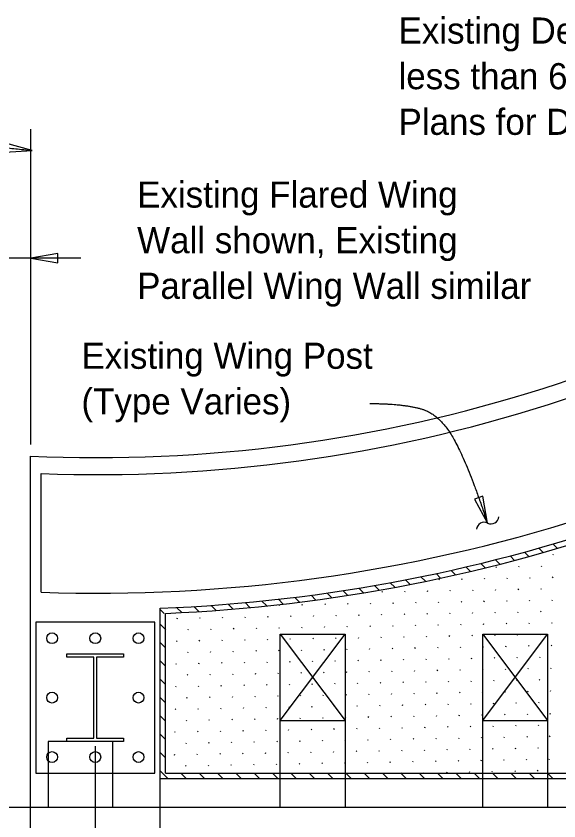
# Model space of a CAD drawing. Extents: x 21526.6 to 21595.9, y 56117 to 56157.3.
# Drawn here: x 21554.19 to 21558.38, y 56146.9 to 56153.11 of the extents above; entities that cross this region are included whole.
import ezdxf

# ---------------------------------------------------------------- set-up
doc = ezdxf.new("R2010")
doc.units = 0
for name, color, linetype in [('AdhocPoint_dp', 7, 'Continuous'), ('Patterning', 7, 'Continuous'), ('PlotBorder_dp', 7, 'Continuous'), ('SheetBorder_dp', 7, 'Continuous')]:
    doc.layers.add(name, color=color, linetype=linetype)

msp = doc.modelspace()

# ---------------------------------------------------------------- linework, layer by layer
at = {"layer": 'AdhocPoint_dp'}
for p, q in [((21554.3018, 56145.2536), (21554.3018, 56149.7195)), ((21554.3851, 56148.6691), (21554.3851, 56149.5851)), ((21555.3018, 56145.2536), (21555.3018, 56148.546)), ((21555.3435, 56147.2732), (21555.3435, 56148.506)), ((21555.3435, 56147.2732), (21562.4118, 56147.2732)), ((21555.3018, 56147.2315), (21562.4118, 56147.2315))]:
    msp.add_line(p, q, dxfattribs=at)
for radius, start, end in [(11.3394, 267.40102, 307.93264), (11.4702, 267.84731, 307.49092), (12.3856, 268.00648, 307.27295), (12.5106, 272.22541, 307.24718), (12.5523, 272.40859, 307.2387)]:
    msp.add_arc((21554.816, 56161.0472), radius, start, end, dxfattribs=at)
at = {"layer": 'Patterning'}
for p, q in [((21558.3332, 56149.0412), (21558.3668, 56149.0077)), ((21558.1128, 56148.9788), (21558.1467, 56148.9449)), ((21558.2234, 56149.0096), (21558.2568, 56148.9763)), ((21557.8889, 56148.9199), (21557.9231, 56148.8856)), ((21558.0013, 56148.9489), (21558.0349, 56148.9152)), ((21558.3327, 56148.9567), (21558.336, 56148.9623)), ((21557.6614, 56148.8645), (21557.696, 56148.8299)), ((21557.7756, 56148.8917), (21557.8096, 56148.8577)), ((21557.8928, 56148.8609), (21557.8961, 56148.8665)), ((21558.0681, 56148.8642), (21558.0714, 56148.8698)), ((21558.2435, 56148.8674), (21558.2467, 56148.873)), ((21557.4303, 56148.8128), (21557.4652, 56148.7778)), ((21557.5463, 56148.8382), (21557.5808, 56148.8037)), ((21557.0763, 56148.7425), (21557.1117, 56148.7071)), ((21557.1953, 56148.7649), (21557.2306, 56148.7296)), ((21557.3133, 56148.7884), (21557.3481, 56148.7535)), ((21557.453, 56148.7652), (21557.4562, 56148.7708)), ((21557.6283, 56148.7684), (21557.6315, 56148.774)), ((21557.8036, 56148.7717), (21557.8068, 56148.7773)), ((21557.9789, 56148.7749), (21557.9821, 56148.7805)), ((21558.1542, 56148.7782), (21558.1574, 56148.7838)), ((21558.3295, 56148.7814), (21558.3327, 56148.787)), ((21556.7132, 56148.6813), (21556.7494, 56148.6451)), ((21556.8353, 56148.7007), (21556.8712, 56148.6648)), ((21556.9563, 56148.7211), (21556.9921, 56148.6853)), ((21557.0131, 56148.6694), (21557.0163, 56148.675)), ((21557.1884, 56148.6727), (21557.1916, 56148.6783)), ((21557.3637, 56148.6759), (21557.3669, 56148.6815)), ((21557.539, 56148.6792), (21557.5422, 56148.6848)), ((21557.7143, 56148.6824), (21557.7175, 56148.688)), ((21557.8896, 56148.6856), (21557.8928, 56148.6912)), ((21558.0649, 56148.6889), (21558.0681, 56148.6945)), ((21558.2402, 56148.6921), (21558.2435, 56148.6977)), ((21556.2139, 56148.615), (21556.2511, 56148.5778)), ((21556.3404, 56148.6298), (21556.3776, 56148.5926)), ((21556.4658, 56148.6459), (21556.5025, 56148.6092)), ((21556.5901, 56148.663), (21556.6266, 56148.6265)), ((21557.9756, 56148.5996), (21557.9789, 56148.6052)), ((21558.1509, 56148.6029), (21558.1542, 56148.6084)), ((21558.3262, 56148.6061), (21558.3295, 56148.6117)), ((21555.4287, 56148.5516), (21555.4682, 56148.5121)), ((21555.5628, 56148.5589), (21555.6017, 56148.52)), ((21555.6956, 56148.5676), (21555.7342, 56148.529)), ((21555.8271, 56148.5775), (21555.8654, 56148.5392)), ((21555.9572, 56148.5888), (21555.9951, 56148.5509)), ((21556.0862, 56148.6013), (21556.1241, 56148.5633)), ((21556.2226, 56148.5672), (21556.2258, 56148.5728)), ((21556.3979, 56148.5704), (21556.4011, 56148.576)), ((21556.5732, 56148.5737), (21556.5764, 56148.5793)), ((21556.7485, 56148.5769), (21556.7518, 56148.5825)), ((21556.9238, 56148.5802), (21556.9271, 56148.5858)), ((21557.0991, 56148.5834), (21557.1024, 56148.589)), ((21557.2744, 56148.5866), (21557.2777, 56148.5922)), ((21557.4497, 56148.5899), (21557.453, 56148.5955)), ((21557.625, 56148.5931), (21557.6283, 56148.5987)), ((21557.8003, 56148.5964), (21557.8036, 56148.602)), ((21555.3018, 56148.5371), (21555.3328, 56148.5061)), ((21555.958, 56148.4747), (21555.9613, 56148.4803)), ((21556.1333, 56148.4779), (21556.1366, 56148.4835)), ((21556.3086, 56148.4812), (21556.3119, 56148.4868)), ((21556.4839, 56148.4844), (21556.4872, 56148.49)), ((21556.6592, 56148.4877), (21556.6625, 56148.4933)), ((21556.8345, 56148.4909), (21556.8378, 56148.4965)), ((21557.0098, 56148.4941), (21557.0131, 56148.4997)), ((21557.1851, 56148.4974), (21557.1884, 56148.503)), ((21557.3605, 56148.5006), (21557.3637, 56148.5062)), ((21557.5358, 56148.5039), (21557.539, 56148.5095)), ((21557.7111, 56148.5071), (21557.7143, 56148.5127)), ((21557.8864, 56148.5103), (21557.8896, 56148.5159)), ((21558.0617, 56148.5136), (21558.0649, 56148.5192)), ((21558.237, 56148.5168), (21558.2402, 56148.5224)), ((21555.3018, 56148.4229), (21555.3435, 56148.3812)), ((21555.4321, 56148.465), (21555.4354, 56148.4706)), ((21555.6074, 56148.4682), (21555.6107, 56148.4738)), ((21555.7827, 56148.4714), (21555.786, 56148.477)), ((21557.2712, 56148.4113), (21557.2744, 56148.4169)), ((21557.4465, 56148.4146), (21557.4497, 56148.4202)), ((21557.6218, 56148.4178), (21557.625, 56148.4234)), ((21557.7971, 56148.4211), (21557.8003, 56148.4267)), ((21557.9724, 56148.4243), (21557.9756, 56148.4299)), ((21558.1477, 56148.4275), (21558.1509, 56148.4331)), ((21558.323, 56148.4308), (21558.3262, 56148.4364)), ((21555.3435, 56148.3768), (21555.3461, 56148.3813)), ((21555.5181, 56148.3789), (21555.5214, 56148.3845)), ((21555.6934, 56148.3822), (21555.6967, 56148.3878)), ((21555.8688, 56148.3854), (21555.872, 56148.391)), ((21556.0441, 56148.3887), (21556.0473, 56148.3943)), ((21556.2194, 56148.3919), (21556.2226, 56148.3975)), ((21556.3947, 56148.3951), (21556.3979, 56148.4007)), ((21556.57, 56148.3984), (21556.5732, 56148.404)), ((21556.7453, 56148.4016), (21556.7485, 56148.4072)), ((21556.9206, 56148.4049), (21556.9238, 56148.4105)), ((21557.0959, 56148.4081), (21557.0991, 56148.4137)), ((21555.4289, 56148.2897), (21555.4321, 56148.2953)), ((21555.6042, 56148.2929), (21555.6074, 56148.2985)), ((21555.7795, 56148.2961), (21555.7827, 56148.3017)), ((21555.9548, 56148.2994), (21555.958, 56148.305)), ((21556.1301, 56148.3026), (21556.1333, 56148.3082)), ((21556.2289, 56147.012), (21556.2289, 56148.3453)), ((21556.2289, 56148.3453), (21556.7289, 56148.3453)), ((21556.2289, 56148.3453), (21556.7289, 56147.6786)), ((21556.2289, 56147.6786), (21556.7289, 56148.3453)), ((21556.3054, 56148.3059), (21556.3086, 56148.3115)), ((21556.4807, 56148.3091), (21556.4839, 56148.3147)), ((21556.656, 56148.3123), (21556.6592, 56148.3179)), ((21556.7289, 56148.3453), (21556.7289, 56147.012)), ((21556.8313, 56148.3156), (21556.8345, 56148.3212)), ((21557.0066, 56148.3188), (21557.0098, 56148.3244)), ((21557.1819, 56148.3221), (21557.1851, 56148.3277)), ((21557.3572, 56148.3253), (21557.3605, 56148.3309)), ((21557.5325, 56148.3286), (21557.5358, 56148.3342)), ((21557.7078, 56148.3318), (21557.7111, 56148.3374)), ((21557.7914, 56147.012), (21557.7914, 56148.3453)), ((21557.7914, 56148.3453), (21558.2914, 56148.3453)), ((21557.7914, 56148.3453), (21558.2914, 56147.6786)), ((21557.7914, 56147.6786), (21558.2914, 56148.3453)), ((21557.8831, 56148.335), (21557.8864, 56148.3406)), ((21558.0584, 56148.3383), (21558.0617, 56148.3439)), ((21558.2337, 56148.3415), (21558.237, 56148.3471)), ((21558.2914, 56148.3453), (21558.2914, 56147.012)), ((21555.3018, 56148.2814), (21555.3435, 56148.2397)), ((21556.742, 56148.2263), (21556.7453, 56148.2319)), ((21556.9173, 56148.2296), (21556.9206, 56148.2352)), ((21557.0926, 56148.2328), (21557.0959, 56148.2384)), ((21557.2679, 56148.236), (21557.2712, 56148.2416)), ((21557.4432, 56148.2393), (21557.4465, 56148.2449)), ((21557.6185, 56148.2425), (21557.6218, 56148.2481)), ((21557.7939, 56148.2458), (21557.7971, 56148.2514)), ((21557.9692, 56148.249), (21557.9724, 56148.2546)), ((21558.1445, 56148.2522), (21558.1477, 56148.2578)), ((21558.3198, 56148.2555), (21558.323, 56148.2611)), ((21555.5149, 56148.2036), (21555.5181, 56148.2092)), ((21555.6902, 56148.2069), (21555.6934, 56148.2125)), ((21555.8655, 56148.2101), (21555.8688, 56148.2157)), ((21556.0408, 56148.2134), (21556.0441, 56148.219)), ((21556.2161, 56148.2166), (21556.2194, 56148.2222)), ((21556.3914, 56148.2198), (21556.3947, 56148.2254)), ((21556.5667, 56148.2231), (21556.57, 56148.2287)), ((21558.0552, 56148.163), (21558.0584, 56148.1686)), ((21558.2305, 56148.1662), (21558.2337, 56148.1718)), ((21555.3018, 56148.14), (21555.3435, 56148.0983)), ((21555.4256, 56148.1144), (21555.4289, 56148.12)), ((21555.6009, 56148.1176), (21555.6042, 56148.1232)), ((21555.7762, 56148.1208), (21555.7795, 56148.1264)), ((21555.9515, 56148.1241), (21555.9548, 56148.1297)), ((21556.1268, 56148.1273), (21556.1301, 56148.1329)), ((21556.3021, 56148.1306), (21556.3054, 56148.1362)), ((21556.4775, 56148.1338), (21556.4807, 56148.1394)), ((21556.6528, 56148.137), (21556.656, 56148.1426)), ((21556.8281, 56148.1403), (21556.8313, 56148.1459)), ((21557.0034, 56148.1435), (21557.0066, 56148.1491)), ((21557.1787, 56148.1468), (21557.1819, 56148.1524)), ((21557.354, 56148.15), (21557.3572, 56148.1556)), ((21557.5293, 56148.1532), (21557.5325, 56148.1588)), ((21557.7046, 56148.1565), (21557.7078, 56148.1621)), ((21557.8799, 56148.1597), (21557.8831, 56148.1653)), ((21556.2129, 56148.0413), (21556.2161, 56148.0469)), ((21556.3882, 56148.0445), (21556.3914, 56148.0501)), ((21556.5635, 56148.0478), (21556.5667, 56148.0534)), ((21556.7388, 56148.051), (21556.742, 56148.0566)), ((21556.9141, 56148.0543), (21556.9173, 56148.0599)), ((21557.0894, 56148.0575), (21557.0926, 56148.0631)), ((21557.2647, 56148.0607), (21557.2679, 56148.0663)), ((21557.44, 56148.064), (21557.4432, 56148.0696)), ((21557.6153, 56148.0672), (21557.6185, 56148.0728)), ((21557.7906, 56148.0705), (21557.7939, 56148.0761)), ((21557.9659, 56148.0737), (21557.9692, 56148.0793)), ((21558.1412, 56148.0769), (21558.1445, 56148.0825)), ((21558.3165, 56148.0802), (21558.3198, 56148.0858)), ((21555.3018, 56147.9986), (21555.3435, 56147.9569)), ((21555.5117, 56148.0283), (21555.5149, 56148.0339)), ((21555.687, 56148.0316), (21555.6902, 56148.0372)), ((21555.8623, 56148.0348), (21555.8655, 56148.0404)), ((21556.0376, 56148.0381), (21556.0408, 56148.0436)), ((21557.526, 56147.9779), (21557.5293, 56147.9835)), ((21557.7013, 56147.9812), (21557.7046, 56147.9868)), ((21557.8766, 56147.9844), (21557.8799, 56147.99)), ((21558.0519, 56147.9877), (21558.0552, 56147.9933)), ((21558.2272, 56147.9909), (21558.2305, 56147.9965)), ((21555.4224, 56147.9391), (21555.4256, 56147.9447)), ((21555.5977, 56147.9423), (21555.6009, 56147.9479)), ((21555.773, 56147.9455), (21555.7762, 56147.9511)), ((21555.9483, 56147.9488), (21555.9515, 56147.9544)), ((21556.1236, 56147.952), (21556.1268, 56147.9576)), ((21556.2989, 56147.9553), (21556.3021, 56147.9609)), ((21556.4742, 56147.9585), (21556.4775, 56147.9641)), ((21556.6495, 56147.9617), (21556.6528, 56147.9673)), ((21556.8248, 56147.965), (21556.8281, 56147.9706)), ((21557.0001, 56147.9682), (21557.0034, 56147.9738)), ((21557.1754, 56147.9715), (21557.1787, 56147.9771)), ((21557.3507, 56147.9747), (21557.354, 56147.9803)), ((21555.5084, 56147.853), (21555.5117, 56147.8586)), ((21555.6837, 56147.8563), (21555.687, 56147.8619)), ((21555.859, 56147.8595), (21555.8623, 56147.8651)), ((21556.0343, 56147.8627), (21556.0376, 56147.8683)), ((21556.2096, 56147.866), (21556.2129, 56147.8716)), ((21556.3849, 56147.8692), (21556.3882, 56147.8748)), ((21556.5602, 56147.8725), (21556.5635, 56147.8781)), ((21556.7355, 56147.8757), (21556.7388, 56147.8813)), ((21556.9109, 56147.879), (21556.9141, 56147.8845)), ((21557.0862, 56147.8822), (21557.0894, 56147.8878)), ((21557.2615, 56147.8854), (21557.2647, 56147.891)), ((21557.4368, 56147.8887), (21557.44, 56147.8943)), ((21557.6121, 56147.8919), (21557.6153, 56147.8975)), ((21557.7874, 56147.8952), (21557.7906, 56147.9008)), ((21557.9627, 56147.8984), (21557.9659, 56147.904)), ((21558.138, 56147.9016), (21558.1412, 56147.9072)), ((21558.3133, 56147.9049), (21558.3165, 56147.9105)), ((21555.3018, 56147.8572), (21555.3435, 56147.8155)), ((21556.9969, 56147.7929), (21557.0001, 56147.7985)), ((21557.1722, 56147.7962), (21557.1754, 56147.8018)), ((21557.3475, 56147.7994), (21557.3507, 56147.805)), ((21557.5228, 56147.8026), (21557.526, 56147.8082)), ((21557.6981, 56147.8059), (21557.7013, 56147.8115)), ((21557.8734, 56147.8091), (21557.8766, 56147.8147)), ((21558.0487, 56147.8124), (21558.0519, 56147.818)), ((21558.224, 56147.8156), (21558.2272, 56147.8212)), ((21555.4191, 56147.7638), (21555.4224, 56147.7693)), ((21555.5945, 56147.767), (21555.5977, 56147.7726)), ((21555.7698, 56147.7702), (21555.773, 56147.7758)), ((21555.9451, 56147.7735), (21555.9483, 56147.7791)), ((21556.1204, 56147.7767), (21556.1236, 56147.7823)), ((21556.2957, 56147.78), (21556.2989, 56147.7856)), ((21556.471, 56147.7832), (21556.4742, 56147.7888)), ((21556.6463, 56147.7864), (21556.6495, 56147.792)), ((21556.8216, 56147.7897), (21556.8248, 56147.7953)), ((21558.31, 56147.7296), (21558.3133, 56147.7352)), ((21555.3018, 56147.7157), (21555.3435, 56147.674)), ((21555.5052, 56147.6777), (21555.5084, 56147.6833)), ((21555.6805, 56147.681), (21555.6837, 56147.6866)), ((21555.8558, 56147.6842), (21555.859, 56147.6898)), ((21556.0311, 56147.6874), (21556.0343, 56147.693)), ((21556.2064, 56147.6907), (21556.2096, 56147.6963)), ((21556.2289, 56147.6786), (21556.7289, 56147.6786)), ((21556.3817, 56147.6939), (21556.3849, 56147.6995)), ((21556.557, 56147.6972), (21556.5602, 56147.7028)), ((21556.7323, 56147.7004), (21556.7355, 56147.706)), ((21556.9076, 56147.7036), (21556.9109, 56147.7092)), ((21557.0829, 56147.7069), (21557.0862, 56147.7125)), ((21557.2582, 56147.7101), (21557.2615, 56147.7157)), ((21557.4335, 56147.7134), (21557.4368, 56147.719)), ((21557.6088, 56147.7166), (21557.6121, 56147.7222)), ((21557.7841, 56147.7199), (21557.7874, 56147.7255)), ((21557.7914, 56147.6786), (21558.2914, 56147.6786)), ((21557.9594, 56147.7231), (21557.9627, 56147.7287)), ((21558.1347, 56147.7263), (21558.138, 56147.7319)), ((21556.2924, 56147.6047), (21556.2957, 56147.6103)), ((21556.4677, 56147.6079), (21556.471, 56147.6135)), ((21556.643, 56147.6111), (21556.6463, 56147.6167)), ((21556.8183, 56147.6144), (21556.8216, 56147.62)), ((21556.9936, 56147.6176), (21556.9969, 56147.6232)), ((21557.1689, 56147.6209), (21557.1722, 56147.6265)), ((21557.3442, 56147.6241), (21557.3475, 56147.6297)), ((21557.5196, 56147.6273), (21557.5228, 56147.6329)), ((21557.6949, 56147.6306), (21557.6981, 56147.6362)), ((21557.8702, 56147.6338), (21557.8734, 56147.6394)), ((21558.0455, 56147.6371), (21558.0487, 56147.6427)), ((21558.2208, 56147.6403), (21558.224, 56147.6459)), ((21555.3018, 56147.5743), (21555.3435, 56147.5326)), ((21555.4159, 56147.5884), (21555.4191, 56147.594)), ((21555.5912, 56147.5917), (21555.5945, 56147.5973)), ((21555.7665, 56147.5949), (21555.7698, 56147.6005)), ((21555.9418, 56147.5982), (21555.9451, 56147.6038)), ((21556.1171, 56147.6014), (21556.1204, 56147.607)), ((21557.7809, 56147.5445), (21557.7841, 56147.5501)), ((21557.9562, 56147.5478), (21557.9594, 56147.5534)), ((21558.1315, 56147.551), (21558.1347, 56147.5566)), ((21558.3068, 56147.5543), (21558.31, 56147.5599)), ((21554.9372, 56147.5174), (21554.4372, 56147.5174)), ((21554.4372, 56147.5174), (21554.4372, 56147.012)), ((21554.9372, 56147.012), (21554.9372, 56147.5174)), ((21555.5019, 56147.5024), (21555.5052, 56147.508)), ((21555.6772, 56147.5057), (21555.6805, 56147.5113)), ((21555.8525, 56147.5089), (21555.8558, 56147.5145)), ((21556.0279, 56147.5121), (21556.0311, 56147.5177)), ((21556.2032, 56147.5154), (21556.2064, 56147.521)), ((21556.3785, 56147.5186), (21556.3817, 56147.5242)), ((21556.5538, 56147.5219), (21556.557, 56147.5275)), ((21556.7291, 56147.5251), (21556.7323, 56147.5307)), ((21556.9044, 56147.5283), (21556.9076, 56147.5339)), ((21557.0797, 56147.5316), (21557.0829, 56147.5372)), ((21557.255, 56147.5348), (21557.2582, 56147.5404)), ((21557.4303, 56147.5381), (21557.4335, 56147.5437)), ((21557.6056, 56147.5413), (21557.6088, 56147.5469)), ((21555.3018, 56147.4329), (21555.3435, 56147.3912)), ((21555.7633, 56147.4196), (21555.7665, 56147.4252)), ((21555.9386, 56147.4229), (21555.9418, 56147.4285)), ((21556.1139, 56147.4261), (21556.1171, 56147.4317)), ((21556.2892, 56147.4293), (21556.2924, 56147.4349)), ((21556.4645, 56147.4326), (21556.4677, 56147.4382)), ((21556.6398, 56147.4358), (21556.643, 56147.4414)), ((21556.8151, 56147.4391), (21556.8183, 56147.4447)), ((21556.9904, 56147.4423), (21556.9936, 56147.4479)), ((21557.1657, 56147.4456), (21557.1689, 56147.4512)), ((21557.341, 56147.4488), (21557.3442, 56147.4544)), ((21557.5163, 56147.452), (21557.5196, 56147.4576)), ((21557.6916, 56147.4553), (21557.6949, 56147.4609)), ((21557.8669, 56147.4585), (21557.8702, 56147.4641)), ((21558.0422, 56147.4618), (21558.0455, 56147.4674)), ((21558.2175, 56147.465), (21558.2208, 56147.4706)), ((21555.4127, 56147.4131), (21555.4159, 56147.4187)), ((21555.588, 56147.4164), (21555.5912, 56147.422)), ((21557.0764, 56147.3563), (21557.0797, 56147.3619)), ((21557.2517, 56147.3595), (21557.255, 56147.3651)), ((21557.427, 56147.3628), (21557.4303, 56147.3684)), ((21557.6023, 56147.366), (21557.6056, 56147.3716)), ((21557.7776, 56147.3692), (21557.7809, 56147.3748)), ((21557.9529, 56147.3725), (21557.9562, 56147.3781)), ((21558.1283, 56147.3757), (21558.1315, 56147.3813)), ((21558.3036, 56147.379), (21558.3068, 56147.3846)), ((21555.4987, 56147.3271), (21555.5019, 56147.3327)), ((21555.674, 56147.3304), (21555.6772, 56147.336)), ((21555.8493, 56147.3336), (21555.8525, 56147.3392)), ((21556.0246, 56147.3368), (21556.0279, 56147.3424)), ((21556.1999, 56147.3401), (21556.2032, 56147.3457)), ((21556.3752, 56147.3433), (21556.3785, 56147.3489)), ((21556.5505, 56147.3466), (21556.5538, 56147.3522)), ((21556.7258, 56147.3498), (21556.7291, 56147.3554)), ((21556.9011, 56147.353), (21556.9044, 56147.3586)), ((21555.3018, 56147.2915), (21555.3617, 56147.2315)), ((21555.4615, 56147.2732), (21555.5032, 56147.2315)), ((21555.6029, 56147.2732), (21555.6446, 56147.2315)), ((21555.7443, 56147.2732), (21555.786, 56147.2315)), ((21555.8857, 56147.2732), (21555.9274, 56147.2315)), ((21556.0272, 56147.2732), (21556.0689, 56147.2315)), ((21556.1686, 56147.2732), (21556.2103, 56147.2315)), ((21556.31, 56147.2732), (21556.3517, 56147.2315)), ((21556.4514, 56147.2732), (21556.4931, 56147.2315)), ((21556.5928, 56147.2732), (21556.6345, 56147.2315)), ((21556.7343, 56147.2732), (21556.776, 56147.2315)), ((21556.8757, 56147.2732), (21556.9174, 56147.2315)), ((21557.0171, 56147.2732), (21557.0588, 56147.2315)), ((21557.1585, 56147.2732), (21557.2002, 56147.2315)), ((21557.1642, 56147.2732), (21557.1657, 56147.2758)), ((21557.2999, 56147.2732), (21557.3416, 56147.2315)), ((21557.3378, 56147.2735), (21557.341, 56147.2791)), ((21557.4414, 56147.2732), (21557.4831, 56147.2315)), ((21557.5131, 56147.2767), (21557.5163, 56147.2823)), ((21557.5828, 56147.2732), (21557.6245, 56147.2315)), ((21557.6884, 56147.28), (21557.6916, 56147.2856)), ((21557.7242, 56147.2732), (21557.7659, 56147.2315)), ((21557.8637, 56147.2832), (21557.8669, 56147.2888)), ((21557.8656, 56147.2732), (21557.9073, 56147.2315)), ((21558.0071, 56147.2732), (21558.0488, 56147.2315)), ((21558.039, 56147.2865), (21558.0422, 56147.2921)), ((21558.1485, 56147.2732), (21558.1902, 56147.2315)), ((21558.2143, 56147.2897), (21558.2175, 56147.2953)), ((21558.2899, 56147.2732), (21558.3316, 56147.2315)), ((21552.8484, 56147.012), (21566.3956, 56147.012))]:
    msp.add_line(p, q, dxfattribs=at)
at = {"layer": 'PlotBorder_dp'}
for p, q in [((21554.3043, 56149.8081), (21554.3043, 56152.2434)), ((21554.6897, 56151.2476), (21550.5899, 56151.2476)), ((21554.8018, 56147.4803), (21554.8018, 56144.9856))]:
    msp.add_line(p, q, dxfattribs=at)
for points in [[(21554.3137, 56152.0784), (21554.11, 56152.1343), (21554.103, 56152.0641)], [(21554.3043, 56151.2476), (21554.5126, 56151.2123), (21554.5126, 56151.2828)], [(21557.8278, 56149.2027), (21557.7926, 56149.4109), (21557.726, 56149.3877)]]:
    msp.add_lwpolyline(points, close=True, dxfattribs=at)
for centre, start, end in [((21557.8551, 56149.2563), 243.37602, 355.10324), ((21557.8017, 56149.1497), 63.37602, 175.10324)]:
    msp.add_arc(centre, 0.0596, start, end, dxfattribs=at)
for points in [[(21553.1921, 56152.3226), (21553.3769, 56152.316), (21553.6144, 56152.217), (21553.6474, 56152.1576), (21553.9178, 56152.118), (21554.3137, 56152.0784)], [(21556.9185, 56150.1252), (21557.1676, 56150.1252), (21557.4603, 56150.0442), (21557.6783, 56149.6515), (21557.8277, 56149.2027)]]:
    msp.add_open_spline(points, degree=2, dxfattribs=at)
at = {"layer": 'SheetBorder_dp'}
msp.add_lwpolyline([(21554.3435, 56147.2726), (21555.2601, 56147.2726), (21555.2601, 56148.4393), (21554.3435, 56148.4393)], close=True, dxfattribs=at)
msp.add_lwpolyline([(21555.0205, 56147.5174), (21554.583, 56147.5174), (21554.583, 56147.5435), (21554.7914, 56147.5435), (21554.7914, 56148.1685), (21554.583, 56148.1685), (21554.583, 56148.1945), (21555.0205, 56148.1945), (21555.0205, 56148.1685), (21554.8122, 56148.1685), (21554.8122, 56147.5435), (21555.0205, 56147.5435), (21555.0205, 56147.5174)], dxfattribs=at)
for centre in [(21554.4685, 56148.3143), (21554.8018, 56148.3143), (21555.1351, 56148.3143), (21554.4685, 56147.856), (21555.1351, 56147.856), (21554.4685, 56147.3976), (21554.8018, 56147.3976), (21555.1351, 56147.3976)]:
    msp.add_circle(centre, 0.0417, dxfattribs=at)

# ---------------------------------------------------------------- texts
at = {"layer": 'PlotBorder_dp'}
for s, p in [('Existing Detached Sidewalk or Integral Sidewalk ', (21557.1409, 56152.9026)), ('less than 6" thick to be removed.  See Roadway ', (21557.1409, 56152.5506)), ('Plans for Details of Sidewalk replacement.', (21557.1409, 56152.1986)), ('Existing Flared Wing ', (21555.1245, 56151.637)), ('Wall shown, Existing ', (21555.1245, 56151.285)), ('Parallel Wing Wall similar', (21555.1245, 56150.933)), ('Existing Wing Post ', (21554.6947, 56150.3933)), ('(Type Varies)', (21554.6947, 56150.0413))]:
    msp.add_text(s, height=0.2016, dxfattribs=at).set_placement(p)

doc.saveas('drawing.dxf')
